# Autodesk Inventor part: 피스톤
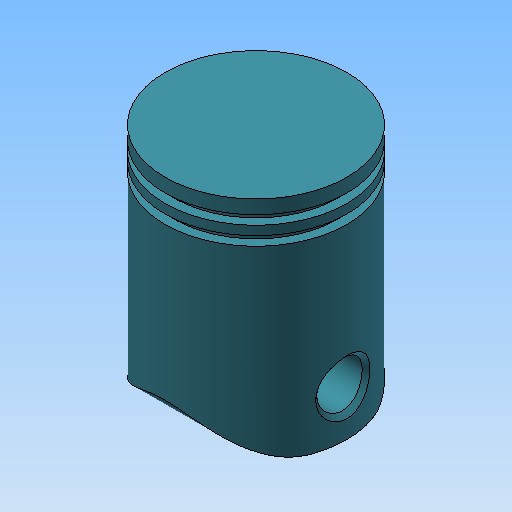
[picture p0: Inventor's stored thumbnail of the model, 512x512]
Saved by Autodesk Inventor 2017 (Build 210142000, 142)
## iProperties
Created: 2017-05
Part Number: 피스톤
Material: 알루미늄 6061
Document SubType Name: Modeling
Designer: mduedu
Density: 2.71 g/cm^3
Mass: 87.7002 g
Surface Area: 150.485 cm^2
Volume: 32.3617 cm^3
Appearance: 커뎃 파란색
Author: mduedu
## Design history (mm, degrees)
sketch "스케치1"
  geometry: L1 (0, 0)-(20, 0); L2 (20, -50)-(15, -50); L3 (15, -50)-(15, -5); L4 (15, -5)-(0, -5); L5 (0, -5)-(0, 0); L6 (20, -3)-(18, -3); L7 (18, -3)-(18, -5); L8 (18, -5)-(20, -5); L9 (20, -7)-(18, -7); L10 (18, -7)-(18, -9); L11 (18, -9)-(20, -9); L12 (20, 0)-(20, -3); L13 (20, -5)-(20, -7); L14 (20, -9)-(20, -50); L15 (0, -60)-(0, 10) reference
  constraints: 28 end point, 10 parallel, 5 perpendicular, 4 collinear, 3 horizontal
  dimensions: "d0" = 20 distance of L1.start L1.end; "d1" = 2 distance of L6.start L6.end; "d2" = 2 distance of L6.end L7.end; "d3" = 2 distance of L8.end L9.start; "d4" = 3 distance of L1.end L6.start; "d5" = 5 distance of L2.start L2.end; "d6" = 50 distance between parallel lines of L1 L2; "d7" = 5 distance of L4.end L1.start
revolve "회전1" sketch "스케치1" stored, may be unused: angle "d8" = 90 deg
fillet "모깎기1" dims "d9" = 1
sketch "스케치2"
  geometry: L1 (-50, 15)-(-50, -15) reference; C1 r 10 at (-40, 0); 1 further point
  constraints: 1 centre point, 1 horizontal alignment
  dimensions: "d10" = 20 diameter of C1; "d11" = 10 distance from line of C1.centre L1
extrude "돌출1" join sketch "스케치2" stored distance "d12" = 10; taper "d13" = 0 deg
sketch "스케치3"
  geometry: L1 (0, -20)-(-3, -20) reference; L2 (-3, -20)-(-3, -18) reference; L3 (-3, -18)-(-5, -18) reference; L4 (-5, -18)-(-5, -20) reference; L5 (-5, -20)-(-7, -20) reference; L6 (-7, -20)-(-7, -18) reference; L7 (-7, -18)-(-9, -18) reference; L8 (-9, -18)-(-9, -20) reference; L9 (-9, -20)-(-50, -20) reference; L10 (-50, -20)-(-50, -15) reference; L11 (-50, -15)-(-6, -15) reference; L12 (-5, -14)-(-5, 14) reference; L13 (-6, 15)-(-50, 15) reference; L14 (-50, 15)-(-50, 20) reference; L15 (-50, 20)-(-9, 20) reference; L16 (-9, 20)-(-9, 18) reference; L17 (-9, 18)-(-7, 18) reference; L18 (-7, 18)-(-7, 20) reference; L19 (-7, 20)-(-5, 20) reference; L20 (-5, 20)-(-5, 18) reference; L21 (-5, 18)-(-3, 18) reference; L22 (-3, 18)-(-3, 20) reference; L23 (-3, 20)-(0, 20) reference; L24 (0, 20)-(0, -20) reference; C1 r 10 at (-40, 0) reference; C2 r 5 at (-40, 0); A1 r 1 centre (-6, -14) between (-6, -15) and (-5, -14) reference; A2 r 1 centre (-6, 14) between (-5, 14) and (-6, 15) reference; 1 further point
  constraints: 1 centre point, 1 coincident
  dimensions: "d15" = 10 diameter of C2
extrude "돌출2" cut sketch "스케치3" stored distance "d16" = 10; taper "d17" = 0 deg
sketch "스케치4"
  geometry: L1 (15, -50)-(-15, -50) reference; L2 (-15, -50)-(-20, -50) reference; L3 (-20, -50)-(-20, -45) reference; L4 (20, -45)-(20, -50) reference; L5 (20, -50)-(15, -50) reference; L6 (-15, -30)-(15, -30) reference; L7 (15, -30)-(15, -6) reference; L8 (14, -5)-(-14, -5) reference; L9 (-15, -6)-(-15, -30) reference; L10 (-20, -3)-(-20, 0) reference; L11 (-20, 0)-(20, 0) reference; L12 (20, 0)-(20, -3) reference; L13 (20, -3)-(18, -3) reference; L14 (18, -3)-(18, -5) reference; L15 (18, -5)-(20, -5) reference; L16 (20, -5)-(20, -7) reference; L17 (20, -7)-(18, -7) reference; L18 (18, -7)-(18, -9) reference; L19 (18, -9)-(20, -9) reference; L20 (-20, -9)-(-18, -9) reference; L21 (-18, -9)-(-18, -7) reference; L22 (-18, -7)-(-20, -7) reference; L23 (-20, -7)-(-20, -5) reference; L24 (-20, -5)-(-18, -5) reference; L25 (-18, -5)-(-18, -3) reference; L26 (-18, -3)-(-20, -3) reference; L27 (0, 0)-(0, -50); L28 (-5.698, -50)-(-5, -30); L29 (5.698, -50)-(5, -30); L30 (-5, -30)-(5, -30); L31 (-5.698, -50)-(5.698, -50); L32 (-20, -45)-(20, -45) reference; L33 (20, -9)-(20, -35) reference; L34 (20, -35)-(-20, -35) reference; L35 (-20, -35)-(-20, -9) reference; A1 r 1 centre (14, -6) between (15, -6) and (14, -5) reference; A2 r 1 centre (-14, -6) between (-14, -5) and (-15, -6) reference
  constraints: 10 end point, 2 point on line, 2 symmetric about line, 1 midpoint, 1 parallel, 1 perpendicular
  dimensions: "d18" = 2 deg angle of L27 L28; "d19" = 5 distance from line of L27 L28.end
extrude "돌출3" cut sketch "스케치4" stored distance "d20" = 20; taper "d21" = 0 deg
chamfer "모따기1" distance "d22" = 1; stored, may be unused: second distance "d23" = 2, angle "d24" = 45 deg
sketch "스케치5"
  geometry: L1 (-50, 0)-(-50, -15) reference; L2 (-50, 15)-(-50, 0) reference; L3 (-9, 20)-(-50, 20) reference; L4 (-50, 20)-(-50, -20) reference; L5 (-9, -20)-(-50, -20) reference; L6 (-42.483, -20)-(-50, -20); L7 (-50, -20)-(-50, -7); L8 (-42.483, 20)-(-50, 20); L9 (-50, 20)-(-50, 7); A1 r 15 centre (-35, 7) between (-42.483, 20) and (-50, 7); A2 r 15 centre (-35, -7) between (-42.483, -20) and (-50, -7); 1 further point
  constraints: 8 end point, 4 point on circle, 4 point on line, 2 centre point, 2 tangent, 1 collinear, 1 equal radius, 1 perpendicular
  dimensions: "d25" = 30 diameter of A1; "d26" = 7 vertical distance of A2.centre point (0, 0); "d27" = 7 vertical distance of point (0, 0) A1.centre (= d26)
extrude "돌출4" cut sketch "스케치5" stored distance "d28" = 20; taper "d29" = 0 deg
node "솔리드1"
node "절단 모서리 투영1"
node "절단 모서리 투영2"
